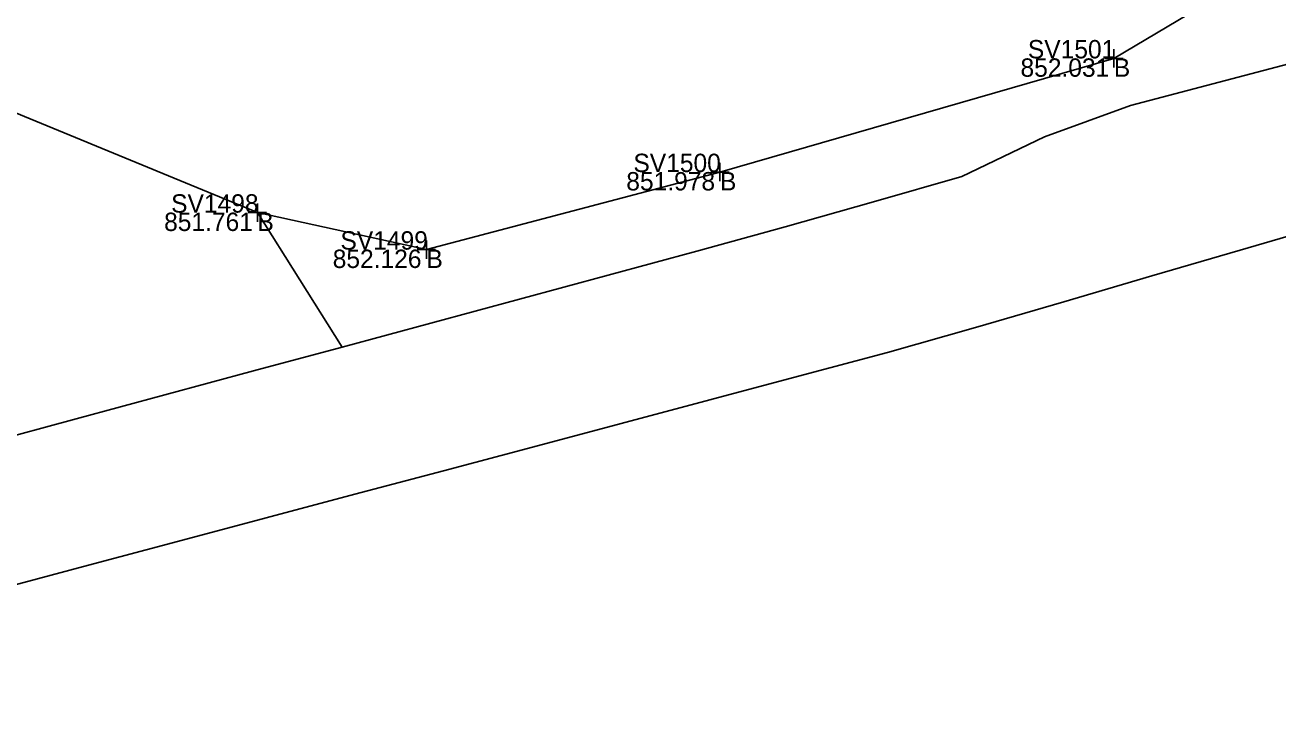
# Model space of a CAD drawing. Extents: x 2125299 to 2129212, y 713100 to 714300.
# Drawn here: x 2128313.4 to 2128381.6, y 713804.8 to 713842.2 of the extents above; entities that cross this region are included whole.
import ezdxf

# ---------------------------------------------------------------- set-up
doc = ezdxf.new("R2010")
doc.units = 0
for name, color, linetype in [('Default', 7, 'Continuous'), ('DT_X_Terrain_Boundary', 7, 'Continuous'), ('PV_X_Field_Drive', 7, 'Continuous'), ('RW_P_Esmt_TMP', 7, 'Continuous'), ('RW_X_Esmt_CH', 7, 'Continuous'), ('RW_X_Fee_WL', 7, 'Continuous'), ('SV_X_Break_Lines', 7, 'Continuous'), ('SV_X_Mon_Cells_Found', 7, 'Continuous')]:
    doc.layers.add(name, color=color, linetype=linetype)

msp = doc.modelspace()

# ---------------------------------------------------------------- linework, layer by layer
at = {"layer": 'Default'}
msp.add_lwpolyline([(2128249.081, 713832.867), (2128285.007, 713846.966), (2128304.036, 713841.037), (2128326.028, 713831.967), (2128330.637, 713824.65), (2128325.81, 713823.347), (2128320.983, 713822.043), (2128316.156, 713820.739), (2128311.329, 713819.435), (2128306.502, 713818.131), (2128301.675, 713816.827), (2128296.848, 713815.523), (2128292.021, 713814.219), (2128287.194, 713812.915), (2128282.367, 713811.611), (2128277.54, 713810.307), (2128272.721, 713808.974), (2128267.915, 713807.594), (2128263.109, 713806.214), (2128258.304, 713804.834)], dxfattribs=at)
at = {"layer": 'DT_X_Terrain_Boundary'}
msp.add_lwpolyline([(2128312.004, 713811.488), (2128316.836, 713812.774), (2128321.668, 713814.059), (2128326.499, 713815.345), (2128331.331, 713816.631), (2128336.163, 713817.916), (2128340.995, 713819.202), (2128345.827, 713820.488), (2128350.659, 713821.773), (2128355.491, 713823.059), (2128360.323, 713824.345), (2128365.13, 713825.717), (2128369.93, 713827.117), (2128374.73, 713828.517), (2128379.53, 713829.917), (2128384.33, 713831.317), (2128389.13, 713832.717), (2128393.93, 713834.117), (2128398.73, 713835.517), (2128403.53, 713836.917), (2128408.33, 713838.319), (2128413.103, 713839.808), (2128417.876, 713841.297)], dxfattribs=at)
at = {"layer": 'PV_X_Field_Drive'}
for points in [[(2128311.329, 713819.435), (2128316.156, 713820.739), (2128320.983, 713822.043), (2128325.81, 713823.347), (2128330.637, 713824.65), (2128335.464, 713825.954), (2128340.291, 713827.258), (2128345.118, 713828.562), (2128349.945, 713829.866), (2128354.764, 713831.199), (2128359.574, 713832.563), (2128364.384, 713833.928), (2128368.878, 713836.103), (2128373.552, 713837.799), (2128378.388, 713839.07), (2128383.224, 713840.339), (2128388.062, 713841.604), (2128392.887, 713842.912), (2128397.688, 713844.308), (2128402.49, 713845.703), (2128407.291, 713847.099), (2128412.092, 713848.494), (2128416.894, 713849.89)], [(2128312.004, 713811.488), (2128316.836, 713812.774), (2128321.668, 713814.059), (2128326.499, 713815.345), (2128331.331, 713816.631), (2128336.163, 713817.916), (2128340.995, 713819.202), (2128345.827, 713820.488), (2128350.659, 713821.773), (2128355.491, 713823.059), (2128360.323, 713824.345), (2128365.13, 713825.717), (2128369.93, 713827.117), (2128374.73, 713828.517), (2128379.53, 713829.917), (2128384.33, 713831.317), (2128389.13, 713832.717), (2128393.93, 713834.117), (2128398.73, 713835.517), (2128403.53, 713836.917), (2128408.33, 713838.319), (2128413.103, 713839.808), (2128417.876, 713841.297)]]:
    msp.add_lwpolyline(points, dxfattribs=at)
at = {"layer": 'SV_X_Break_Lines'}
msp.add_lwpolyline([(2128285.007, 713846.966), (2128304.036, 713841.037), (2128326.028, 713831.967), (2128335.229, 713829.953), (2128351.209, 713834.175), (2128372.654, 713840.365), (2128397.041, 713854.87), (2128424.528, 713863.803), (2128437.965, 713867.069)], dxfattribs=at)
at = {"layer": 'SV_X_Mon_Cells_Found'}
for p, q in [((2128372.154, 713840.365), (2128373.154, 713840.365)), ((2128372.654, 713840.865), (2128372.654, 713839.865)), ((2128372.654, 713840.365), (2128372.654, 713840.365)), ((2128350.709, 713834.175), (2128351.709, 713834.175)), ((2128351.209, 713834.675), (2128351.209, 713833.675)), ((2128351.209, 713834.175), (2128351.209, 713834.175)), ((2128326.028, 713832.467), (2128326.028, 713831.467)), ((2128325.528, 713831.967), (2128326.528, 713831.967)), ((2128326.028, 713831.967), (2128326.028, 713831.967)), ((2128335.229, 713830.453), (2128335.229, 713829.453)), ((2128334.729, 713829.953), (2128335.729, 713829.953)), ((2128335.229, 713829.953), (2128335.229, 713829.953))]:
    msp.add_line(p, q, dxfattribs=at)

# ---------------------------------------------------------------- texts
at = {"layer": 'RW_P_Esmt_TMP'}
for p in [(2128372.654, 713839.365), (2128351.209, 713833.175), (2128326.028, 713830.967), (2128335.229, 713828.953)]:
    msp.add_text('B', height=1, dxfattribs=at).set_placement(p)
at = {"layer": 'RW_X_Esmt_CH'}
for s, p in [('SV1501', (2128367.974, 713840.365)), ('SV1500', (2128346.497, 713834.175)), ('SV1498', (2128321.329, 713831.967)), ('SV1499', (2128330.547, 713829.953))]:
    msp.add_text(s, height=1, dxfattribs=at).set_placement(p)
at = {"layer": 'RW_X_Fee_WL'}
for s, p in [('852.031', (2128367.572, 713839.365)), ('851.978', (2128346.109, 713833.175)), ('851.761', (2128320.946, 713830.967)), ('852.126', (2128330.125, 713828.953))]:
    msp.add_text(s, height=1, dxfattribs=at).set_placement(p)

doc.saveas('drawing.dxf')
